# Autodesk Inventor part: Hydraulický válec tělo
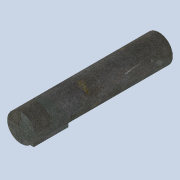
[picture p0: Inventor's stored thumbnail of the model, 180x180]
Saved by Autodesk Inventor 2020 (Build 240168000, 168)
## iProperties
Created: 2025-03
Part Number: Hydraulický válec tělo
Material: Ocel
Document SubType Name: Modeling
Designer: doma
Density: 7.85 g/cm^3
Appearance: Plech
Mass: 247.566 g
Surface Area: 288.085 cm^2
Volume: 247.566 cm^3
Author: doma
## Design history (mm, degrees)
sketch "Náčrt1"
  geometry: C1 r 20 at (0, 0); 1 further point
  constraints: 1 centre point, 1 coincident
  dimensions: "d0" = 40 diameter of C1
extrude "Vysunutí1" new body sketch "Náčrt1" distance "d1" = 200; taper "d2" = 0 deg
sketch "Náčrt2"
  geometry: L1 (20, 0)-(-20, 0) reference; C1 r 5.5 at (0, 20); 1 further point
  constraints: 1 centre point
  dimensions: "d3" = 11 diameter of C1; "d6" = 20 distance from line of L1 C1.centre
extrude "Vysunutí2" cut sketch "Náčrt2" extent not by distance; stored distance "d4" = 20; taper "d5" = 0 deg
sketch "Náčrt3"
  geometry: L1 (8.5, 140)-(-8.5, 140); L2 (-8.5, 140)-(-8.5, 190); L3 (-8.5, 190)-(8.5, 190); L4 (8.5, 190)-(8.5, 140); L5 (8.5, 140)-(-8.5, 190); L6 (-8.5, 140)-(8.5, 190); L7 (20, 200)-(-20, 200) reference; 2 further points
  constraints: 12 end point, 2 midpoint, 2 parallel, 1 horizontal, 1 perpendicular
  dimensions: "d7" = 17 distance of L2.end L3.end; "d8" = 50 distance of L1.end L2.end; "d9" = 10 distance between parallel lines of L7 L3
extrude "Vysunutí3" join sketch "Náčrt3" distance "d10" = 25; taper "d11" = 0 deg
sketch "Náčrt4"
  geometry: 1 further point
sketch "Náčrt5"
  geometry: L1 (8.5, 190)-(-8.5, 190) reference; L2 (0, 190)-(0, 180.5); L3 (-8.5, 140)-(8.5, 140) reference; L4 (0, 140)-(0, 149.5); 1 further point
  constraints: 4 end point, 2 midpoint, 2 vertical, 1 collinear
  dimensions: "d12" = 31 distance of L4.end L2.end
hole "Díra1" sketch "Náčrt5" at (0, 180.5), (0, 149.5) diameter "d13" = 4.134; stored, may be unused: countersink angle "d17" = 90 deg, drill point angle "d19" = 0 deg; dims "d14" = 5, "d15" = 4, "d16" = 2, "d18" = 5
node "Těleso1"
